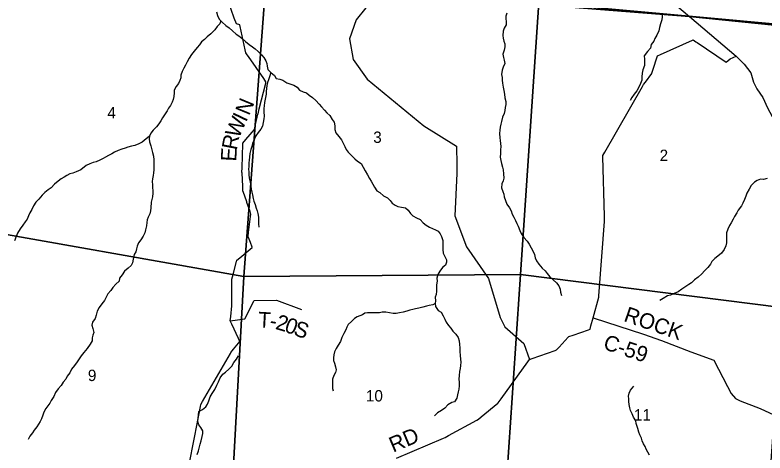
# Model space of a CAD drawing. Extents: x 1715311 to 2083412, y 146837 to 553079.
# Drawn here: x 1902630 to 1917185, y 398764 to 407256 of the extents above; entities that cross this region are included whole.
import ezdxf

# ---------------------------------------------------------------- set-up
doc = ezdxf.new("R2010")
doc.units = 0
for name, color, linetype in [('GM_X_County_Road', 7, 'Continuous'), ('GM_X_County_Road_Text', 7, 'Continuous'), ('GM_X_Minor_River', 7, 'Continuous'), ('GM_X_Section', 7, 'Continuous'), ('GM_X_Section_Text', 7, 'Continuous'), ('GM_X_Township', 7, 'Continuous'), ('GM_X_Township_Road', 7, 'Continuous'), ('GM_X_Township_Road_Text', 7, 'Continuous'), ('GM_X_US_Route', 7, 'Continuous')]:
    doc.layers.add(name, color=color, linetype=linetype)

msp = doc.modelspace()

# ---------------------------------------------------------------- linework, layer by layer
at = {"layer": 'GM_X_County_Road'}
for points in [[(1913849, 401384), (1913958, 401788), (1913963, 401809), (1913969, 401892), (1914071, 403250), (1914073, 403277), (1914071, 403354), (1914036, 404505), (1914035, 404530), (1914075, 404599), (1914807, 405870), (1914830, 405910), (1914864, 405957), (1914990, 406124), (1914992, 406127), (1915023, 406223), (1915087, 406423), (1915100, 406464), (1915157, 406489), (1915778, 406766), (1915794, 406773), (1915845, 406739)], [(1915845, 406739), (1915867, 406724), (1916430, 406342), (1916430, 406342), (1916512, 406406), (1916627, 406459)], [(1910033, 398665), (1910949, 399053), (1910978, 399065), (1911042, 399100), (1911592, 399403), (1911624, 399420), (1911677, 399464), (1912001, 399729), (1912005, 399733), (1912063, 399813), (1912585, 400534), (1912615, 400576), (1912666, 400593), (1913110, 400751), (1913141, 400762), (1913189, 400815), (1913367, 401007), (1913381, 401023), (1913460, 401050), (1913757, 401154), (1913791, 401165), (1913808, 401232), (1913849, 401384)], [(1913849, 401384), (1914830, 401068), (1915179, 400947), (1915745, 400727), (1916192, 400562), (1916456, 400052), (1916527, 399919), (1916613, 399818), (1916706, 399778), (1917094, 399626), (1917356, 399501)]]:
    msp.add_lwpolyline(points, dxfattribs=at)
at = {"layer": 'GM_X_Minor_River'}
for points in [[(1906540, 407320), (1906563, 407244), (1906595, 407176), (1906652, 407115), (1906720, 407055), (1906786, 407010), (1906851, 406952), (1906923, 406887), (1906974, 406855), (1907040, 406798), (1907101, 406740), (1907173, 406685), (1907239, 406639), (1907290, 406602), (1907350, 406548), (1907411, 406483), (1907459, 406433), (1907500, 406365), (1907516, 406315), (1907524, 406262), (1907537, 406198), (1907595, 406142), (1907666, 406083), (1907698, 406027), (1907772, 406014), (1907830, 405990), (1907905, 405940), (1907983, 405913), (1908039, 405897), (1908108, 405860), (1908152, 405796), (1908220, 405769), (1908287, 405745), (1908341, 405702), (1908401, 405658), (1908470, 405597), (1908532, 405527), (1908579, 405474), (1908637, 405414), (1908682, 405362), (1908738, 405305), (1908785, 405229), (1908825, 405178), (1908839, 405108), (1908840, 405038), (1908858, 404970), (1908913, 404901), (1908967, 404837), (1909004, 404761), (1909030, 404706), (1909059, 404650), (1909095, 404598), (1909160, 404529), (1909222, 404469), (1909275, 404422), (1909345, 404374), (1909388, 404304), (1909426, 404235), (1909471, 404157), (1909511, 404087), (1909542, 404034), (1909576, 403976)], [(1912172, 407289), (1912154, 407235), (1912155, 407183), (1912165, 407133), (1912160, 407067), (1912124, 406999), (1912102, 406941), (1912099, 406861), (1912103, 406809), (1912116, 406751), (1912134, 406700), (1912136, 406642), (1912121, 406572), (1912099, 406496), (1912108, 406432), (1912126, 406382), (1912139, 406318), (1912103, 406248), (1912083, 406188), (1912074, 406102), (1912084, 406044), (1912087, 405992), (1912091, 405932), (1912102, 405860), (1912120, 405795), (1912129, 405721), (1912133, 405649), (1912158, 405577), (1912154, 405523), (1912144, 405465), (1912133, 405405), (1912121, 405349), (1912094, 405275), (1912074, 405189), (1912057, 405137), (1912045, 405081), (1912041, 405021), (1912034, 404957), (1912038, 404877), (1912043, 404823), (1912053, 404763), (1912060, 404708), (1912050, 404640), (1912050, 404572), (1912045, 404502), (1912061, 404432), (1912074, 404378), (1912094, 404304), (1912103, 404252), (1912111, 404179), (1912116, 404095), (1912104, 404041), (1912077, 403983), (1912071, 403907), (1912098, 403835), (1912114, 403785), (1912126, 403729), (1912149, 403659), (1912177, 403590), (1912228, 403514), (1912258, 403456), (1912281, 403395), (1912309, 403339), (1912340, 403271), (1912370, 403213), (1912394, 403160), (1912425, 403080), (1912455, 403018), (1912504, 402939), (1912567, 402869), (1912609, 402813), (1912650, 402742), (1912682, 402686), (1912709, 402612), (1912727, 402545), (1912753, 402489), (1912796, 402423), (1912860, 402348), (1912917, 402294), (1912957, 402244), (1913008, 402177), (1913072, 402123), (1913137, 402066), (1913183, 402004), (1913208, 401942), (1913218, 401885), (1913238, 401819)], [(1915189, 407279), (1915190, 407219), (1915180, 407163), (1915159, 407083), (1915139, 407015), (1915125, 406951), (1915088, 406867), (1915044, 406802), (1915025, 406746), (1914979, 406682), (1914960, 406616), (1914908, 406546), (1914842, 406465), (1914845, 406398), (1914849, 406340), (1914844, 406278), (1914816, 406196), (1914801, 406130), (1914795, 406060), (1914796, 405992), (1914770, 405926), (1914742, 405868), (1914695, 405787), (1914649, 405719), (1914604, 405659), (1914568, 405597)], [(1906626, 407143), (1906602, 407088), (1906556, 407032), (1906506, 406966), (1906431, 406891), (1906359, 406835), (1906307, 406781), (1906248, 406738), (1906210, 406680), (1906168, 406628), (1906107, 406554), (1906053, 406491), (1906008, 406421), (1905972, 406345), (1905938, 406281), (1905909, 406227), (1905875, 406159), (1905850, 406091), (1905848, 406041), (1905830, 405987), (1905801, 405928), (1905755, 405872), (1905720, 405796), (1905718, 405744), (1905712, 405676), (1905699, 405618), (1905679, 405564), (1905648, 405504), (1905608, 405452), (1905582, 405400), (1905543, 405343), (1905493, 405265), (1905457, 405203), (1905422, 405145), (1905376, 405091), (1905312, 405026), (1905265, 404962), (1905239, 404910), (1905231, 404858), (1905240, 404798), (1905264, 404722), (1905283, 404639), (1905299, 404587), (1905318, 404519), (1905324, 404451), (1905325, 404395), (1905324, 404251), (1905316, 404199), (1905312, 404143), (1905299, 404081), (1905293, 404029), (1905298, 403966), (1905300, 403906), (1905302, 403854), (1905305, 403800), (1905301, 403732), (1905270, 403630), (1905269, 403518), (1905259, 403458), (1905245, 403400), (1905212, 403338), (1905192, 403286), (1905187, 403230), (1905179, 403168), (1905165, 403090), (1905148, 403032), (1905118, 402966), (1905069, 402895), (1905029, 402841), (1904999, 402775), (1904990, 402719), (1904974, 402665), (1904945, 402613), (1904925, 402521), (1904910, 402451), (1904886, 402399), (1904826, 402346), (1904757, 402288), (1904713, 402216), (1904659, 402152), (1904652, 402092), (1904584, 402035), (1904526, 401975), (1904489, 401917), (1904433, 401850), (1904406, 401798), (1904368, 401720), (1904318, 401656), (1904265, 401582), (1904227, 401511), (1904208, 401437), (1904186, 401373), (1904133, 401303), (1904121, 401243), (1904139, 401177), (1904160, 401100), (1904138, 401049), (1904125, 400995), (1904125, 400938), (1904092, 400871), (1904030, 400789)], [(1907595, 406142), (1907570, 406058), (1907550, 406002), (1907532, 405948), (1907519, 405892), (1907513, 405834), (1907506, 405772), (1907502, 405722), (1907492, 405654), (1907475, 405562), (1907467, 405494), (1907460, 405444), (1907456, 405376), (1907465, 405296), (1907461, 405240), (1907448, 405174), (1907432, 405100), (1907400, 405040), (1907349, 404978), (1907305, 404912), (1907278, 404854), (1907240, 404762), (1907223, 404706), (1907207, 404647), (1907189, 404571), (1907182, 404501), (1907174, 404440), (1907171, 404388), (1907165, 404318), (1907164, 404268), (1907166, 404214), (1907168, 404164), (1907177, 404092), (1907191, 404018), (1907204, 403936), (1907214, 403880), (1907227, 403823), (1907237, 403769), (1907253, 403701), (1907264, 403645), (1907288, 403585), (1907311, 403510), (1907329, 403458), (1907340, 403408), (1907354, 403334), (1907354, 403280), (1907353, 403210), (1907361, 403144)], [(1905237, 404898), (1905173, 404854), (1905100, 404791), (1905036, 404757), (1904956, 404728), (1904890, 404710), (1904820, 404691), (1904770, 404675), (1904702, 404657), (1904630, 404630), (1904559, 404596), (1904507, 404566), (1904447, 404535), (1904389, 404499), (1904339, 404471), (1904279, 404442), (1904207, 404410), (1904148, 404393), (1904080, 404371), (1904008, 404338), (1903906, 404252), (1903820, 404213), (1903751, 404187), (1903695, 404175), (1903637, 404144), (1903581, 404112), (1903529, 404080), (1903467, 404037), (1903398, 403973), (1903330, 403906), (1903272, 403864), (1903207, 403814), (1903155, 403760), (1903095, 403687), (1903032, 403627), (1902988, 403557), (1902954, 403487), (1902921, 403418), (1902895, 403360), (1902864, 403296), (1902826, 403244), (1902782, 403184), (1902733, 403108), (1902681, 403027), (1902654, 402959), (1902622, 402879)], [(1917229, 404084), (1917159, 404069), (1917099, 404071), (1917035, 404047), (1916983, 404016), (1916918, 403952), (1916878, 403880), (1916831, 403800), (1916813, 403742), (1916789, 403680), (1916756, 403609), (1916732, 403557), (1916667, 403473), (1916639, 403421), (1916592, 403347), (1916568, 403295), (1916530, 403226), (1916499, 403174), (1916465, 403106), (1916438, 403030), (1916438, 402968), (1916440, 402900), (1916435, 402840), (1916423, 402782), (1916392, 402710), (1916338, 402636), (1916272, 402578), (1916209, 402533), (1916153, 402475), (1916125, 402423), (1916078, 402359), (1916014, 402294), (1915958, 402236), (1915885, 402174), (1915817, 402119), (1915759, 402061), (1915704, 402029), (1915652, 401992), (1915574, 401938), (1915502, 401891), (1915424, 401859), (1915351, 401825), (1915293, 401808), (1915211, 401760), (1915145, 401719)], [(1909576, 403976), (1909606, 403916), (1909655, 403849), (1909711, 403817), (1909782, 403750), (1909856, 403712), (1909914, 403659), (1909951, 403607), (1910005, 403567), (1910057, 403546), (1910128, 403530), (1910206, 403515), (1910262, 403473), (1910307, 403410), (1910351, 403360), (1910419, 403324), (1910490, 403293), (1910550, 403229), (1910608, 403178), (1910677, 403142), (1910735, 403115), (1910789, 403091), (1910840, 403064), (1910878, 403012), (1910910, 402960), (1910933, 402882), (1910933, 402822), (1910934, 402771), (1910934, 402711), (1910939, 402637), (1910973, 402575), (1911007, 402511), (1911004, 402461), (1910986, 402407), (1910926, 402357), (1910877, 402287), (1910835, 402223), (1910818, 402155), (1910820, 402097), (1910807, 402027), (1910811, 401977), (1910813, 401899), (1910802, 401837), (1910786, 401785), (1910793, 401715), (1910787, 401663), (1910793, 401605), (1910844, 401529), (1910902, 401494), (1910941, 401426), (1910975, 401361), (1910996, 401297), (1911044, 401235), (1911085, 401183), (1911125, 401128), (1911187, 401070), (1911228, 401001), (1911250, 400941), (1911259, 400867), (1911265, 400801), (1911266, 400731), (1911268, 400657), (1911277, 400583), (1911285, 400522), (1911276, 400460), (1911272, 400402), (1911258, 400344), (1911247, 400264), (1911246, 400194), (1911252, 400136), (1911252, 400066), (1911245, 400004), (1911231, 399948), (1911220, 399894), (1911204, 399824), (1911158, 399756), (1911108, 399743), (1911033, 399695), (1910975, 399631), (1910907, 399588), (1910832, 399540), (1910774, 399482)], [(1910787, 401659), (1910741, 401635), (1910669, 401624), (1910613, 401608), (1910545, 401591), (1910467, 401571), (1910405, 401561), (1910353, 401548), (1910291, 401530), (1910235, 401513), (1910166, 401495), (1910094, 401483), (1910028, 401470), (1909968, 401466), (1909901, 401479), (1909825, 401497), (1909755, 401492), (1909703, 401484), (1909631, 401480), (1909549, 401479), (1909471, 401484), (1909421, 401472), (1909371, 401442), (1909321, 401422), (1909271, 401401), (1909221, 401371), (1909158, 401313), (1909096, 401258), (1909070, 401206), (1909051, 401152), (1909013, 401082), (1908976, 401002), (1908946, 400928), (1908899, 400851), (1908861, 400789), (1908833, 400727), (1908818, 400667), (1908812, 400609), (1908813, 400555), (1908831, 400503), (1908847, 400434), (1908862, 400376), (1908850, 400322), (1908820, 400268), (1908789, 400196), (1908789, 400128), (1908792, 400072), (1908794, 400016), (1908803, 399966)], [(1904030, 400789), (1903966, 400711), (1903917, 400650), (1903875, 400590), (1903838, 400532), (1903784, 400460), (1903728, 400390), (1903697, 400319), (1903641, 400251), (1903614, 400195), (1903566, 400137), (1903524, 400073), (1903465, 400008), (1903413, 399936), (1903382, 399860), (1903332, 399780), (1903306, 399728), (1903267, 399675), (1903229, 399623), (1903192, 399555), (1903170, 399499), (1903146, 399427), (1903121, 399375), (1903085, 399323), (1903051, 399272), (1903000, 399206), (1902972, 399154), (1902918, 399090), (1902887, 399024)], [(1906166, 398732), (1906190, 398806), (1906213, 398880), (1906225, 398934), (1906240, 399000), (1906262, 399080), (1906276, 399144), (1906275, 399196), (1906235, 399258), (1906200, 399311), (1906180, 399377), (1906185, 399441), (1906193, 399505), (1906199, 399569), (1906268, 399609), (1906332, 399660), (1906366, 399712), (1906391, 399772), (1906417, 399850), (1906454, 399914), (1906508, 399997), (1906545, 400077), (1906579, 400145), (1906611, 400221), (1906664, 400293), (1906714, 400332), (1906778, 400390), (1906837, 400448), (1906877, 400516), (1906928, 400583), (1906970, 400649)], [(1914941, 398722), (1914913, 398777), (1914879, 398837), (1914858, 398887), (1914830, 398943), (1914803, 398998), (1914787, 399048), (1914754, 399118), (1914736, 399168), (1914720, 399240), (1914687, 399335), (1914677, 399385), (1914634, 399455), (1914606, 399523), (1914575, 399590), (1914563, 399640), (1914552, 399702), (1914542, 399762), (1914540, 399812), (1914539, 399864), (1914551, 399922), (1914578, 399984), (1914640, 400058)]]:
    msp.add_lwpolyline(points, dxfattribs=at)
at = {"layer": 'GM_X_Section'}
for points in [[(1913162, 412614), (1918425, 412252), (1918048, 407020), (1912798, 407499)], [(1901943, 408375), (1907500, 407886), (1907073, 402184), (1901506, 403171)], [(1907500, 407886), (1912798, 407499), (1912443, 402225), (1907073, 402184)], [(1912798, 407499), (1918048, 407020), (1918144, 407016), (1917506, 401587), (1912443, 402225)], [(1901506, 403171), (1907073, 402184), (1906832, 397824), (1901104, 398166)], [(1907073, 402184), (1912443, 402225), (1912119, 397444), (1906832, 397824)], [(1912443, 402225), (1917506, 401587), (1917189, 397031), (1916893, 397046), (1912119, 397444)]]:
    msp.add_lwpolyline(points, close=True, dxfattribs=at)
at = {"layer": 'GM_X_Township'}
for points in [[(1923575, 409917), (1923291, 406654), (1918295, 406988), (1918001, 406997), (1915721, 407225), (1912759, 407460)], [(1912759, 407460), (1915721, 407225), (1918001, 406997), (1918295, 406988), (1923291, 406654), (1922814, 401187), (1922676, 399544), (1922667, 399433), (1922654, 399275), (1922642, 399134), (1922627, 398958), (1922601, 398654), (1922365, 395839), (1922091, 391805), (1921923, 390465)]]:
    msp.add_lwpolyline(points, dxfattribs=at)
at = {"layer": 'GM_X_Township_Road'}
for points in [[(1910074, 409814), (1910003, 409738), (1909988, 409725), (1909764, 409419), (1909505, 408808), (1909479, 408721), (1909585, 408417), (1909600, 408343), (1909600, 408239), (1909525, 407735), (1909477, 407466), (1909439, 407396), (1909252, 407162), (1909121, 406796), (1909191, 406392), (1909466, 406012), (1910563, 405106), (1911200, 404713), (1911204, 404349)], [(1907160, 406453), (1907137, 406487), (1907113, 406522), (1907100, 406581), (1907003, 407033), (1906996, 407066), (1906930, 407085), (1906886, 407192), (1906824, 407364), (1906795, 407466), (1906778, 407542), (1906780, 407627), (1906791, 407725), (1906829, 407936), (1906832, 407959)], [(1907132, 403618), (1907126, 403634), (1907057, 403833), (1907054, 403841), (1907049, 403935), (1907036, 404192), (1907035, 404210), (1907038, 404295), (1907054, 404757), (1907054, 404773), (1907110, 404839), (1907275, 405035), (1907277, 405037), (1907299, 405135), (1907345, 405335), (1907346, 405337), (1907370, 405435), (1907495, 405933), (1907501, 405958), (1907457, 406022), (1907160, 406453)], [(1911204, 404349), (1911204, 404292), (1911205, 404185), (1911165, 403364), (1911392, 402763), (1911817, 402148), (1912046, 401392), (1912136, 401212), (1912507, 400884), (1912615, 400576)], [(1905983, 398408), (1906135, 399163), (1906142, 399199), (1906154, 399264), (1906232, 399668), (1906239, 399704), (1906272, 399761), (1906811, 400695), (1906821, 400714), (1906873, 400777), (1906970, 400896), (1906996, 400927), (1906970, 400984), (1906840, 401263), (1906808, 401329), (1906817, 401410), (1906839, 401614), (1906841, 401627), (1906841, 402132), (1906866, 402227), (1906931, 402475), (1906938, 402501), (1906996, 402550), (1907230, 402751), (1907235, 402755), (1907199, 402845), (1907162, 402940), (1907152, 402967), (1907162, 403041), (1907203, 403346), (1907210, 403394), (1907192, 403445), (1907132, 403618)], [(1906808, 401329), (1907090, 401367), (1907274, 401722), (1907703, 401724), (1908188, 401548)]]:
    msp.add_lwpolyline(points, dxfattribs=at)
at = {"layer": 'GM_X_US_Route'}
msp.add_lwpolyline([(1914950, 407882), (1915721, 407225), (1916627, 406459), (1916780, 406306), (1916912, 406137), (1916960, 405956), (1917028, 405826), (1917140, 405656), (1917236, 405455), (1917464, 405026), (1917599, 404795), (1917835, 404447), (1918019, 404242), (1918213, 404011), (1918706, 403400), (1918960, 403072), (1919229, 402731), (1919473, 402383), (1919610, 402165), (1919773, 401927), (1920259, 401206)], dxfattribs=at)

# ---------------------------------------------------------------- texts
at = {"layer": 'GM_X_County_Road_Text'}
for s, rotation, p in [('ROCK', 340.9385, (1914427, 401326)), ('C-59', 341.7827, (1914027, 400785)), ('RD', 23.0753, (1909969, 398768))]:
    msp.add_text(s, height=300, rotation=rotation, dxfattribs=at).set_placement(p)
at = {"layer": 'GM_X_Section_Text'}
for s, p in [('4', (1904423, 405251)), ('3', (1909582, 404776)), ('2', (1915141, 404424)), ('9', (1904045, 400158)), ('10', (1909441, 399762)), ('11', (1914642, 399393))]:
    msp.add_text(s, height=221, rotation=0, dxfattribs=at).set_placement(p)
at = {"layer": 'GM_X_Township_Road_Text'}
for s, rotation, p in [('N', 67.449, (1907172, 405293)), ('W', 66.4243, (1906974, 404850)), ('I', 64.4823, (1907112, 405166)), ('R', 79.1118, (1906933, 404625)), ('E', 87.2647, (1906923, 404412)), ('T', 356.6979, (1907342, 401203)), ('2', 343.4897, (1907669, 401172)), ('-', 350.0938, (1907557, 401192)), ('0', 340.1877, (1907842, 401121)), ('S', 340.1877, (1908016, 401059))]:
    msp.add_text(s, height=300, rotation=rotation, dxfattribs=at).set_placement(p)

doc.saveas('drawing.dxf')
